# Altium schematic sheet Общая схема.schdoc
size 247 x 172 mm
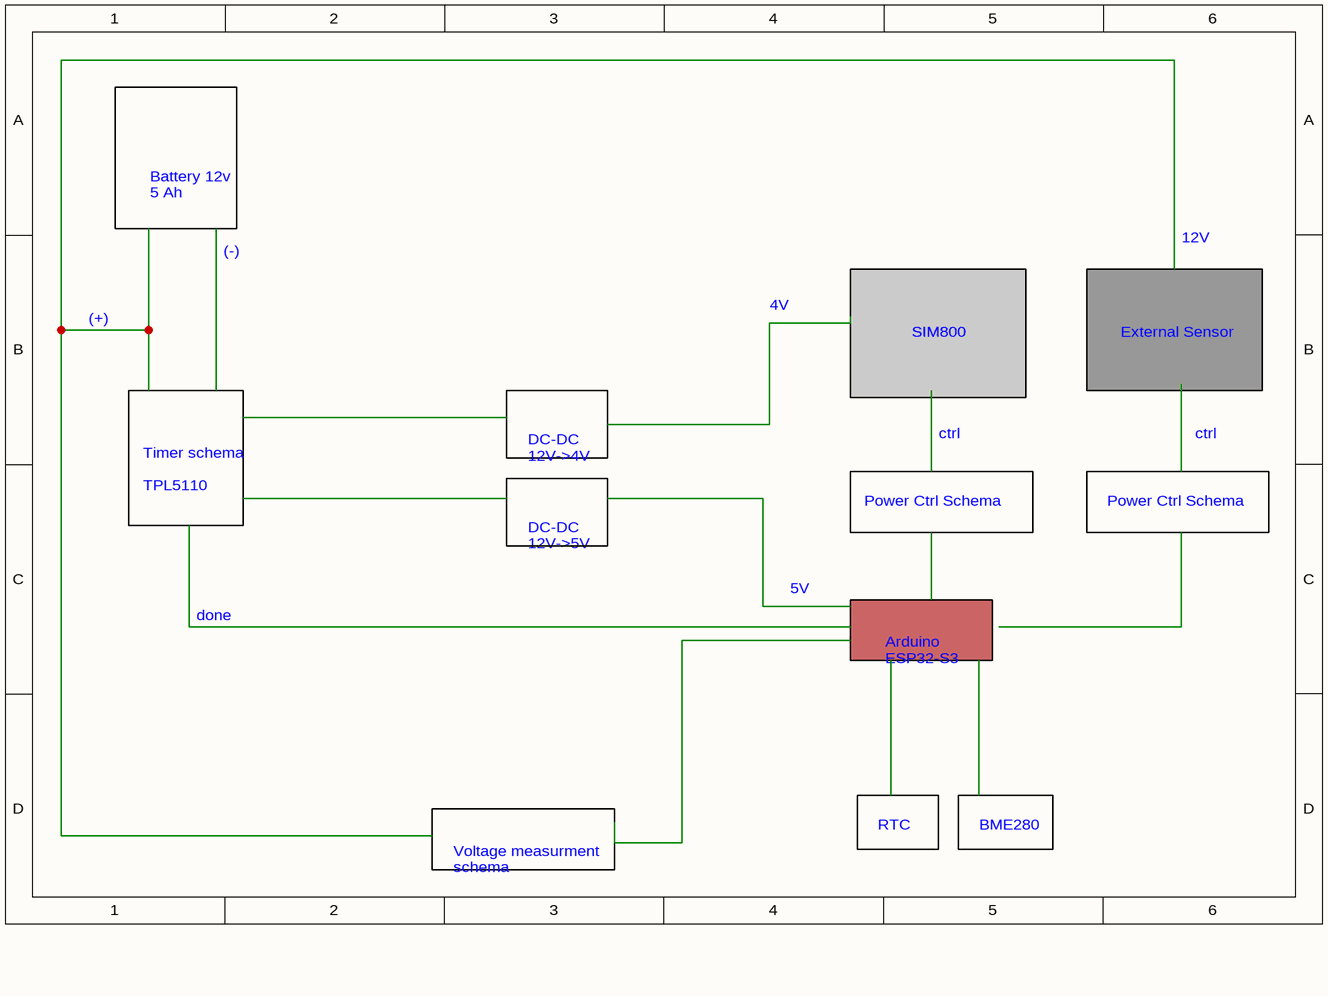
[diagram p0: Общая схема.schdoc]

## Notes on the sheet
- Battery 12v
  5 Ah
- (-)
- 12V
- (+)
- 4V
- SIM800
- External Sensor
- Timer schema
  TPL5110
- DC-DC
  12V->4V
- ctrl
- DC-DC
  12V->5V
- Power Ctrl Schema
- 5V
- done
- Arduino
  ESP32-S3
- Voltage measurment
  schema
- RTC
- BME280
